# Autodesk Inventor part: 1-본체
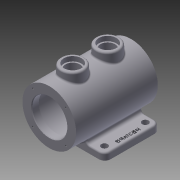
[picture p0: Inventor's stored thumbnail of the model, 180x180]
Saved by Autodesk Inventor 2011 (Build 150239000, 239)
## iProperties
Created: 2014-12
Part Number: 1-본체
Document SubType Name: Modeling
Designer: user
Density: 2.71 g/cm^3
Material: 알루미늄-6061
Mass: 1310.14 g
Surface Area: 1060.2 cm^2
Volume: 483.445 cm^3
Author: user
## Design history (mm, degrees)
sketch "스케치1"
  geometry: L1 (-47.5, 65)-(47.5, 65); L2 (47.5, 65)-(47.5, -65); L3 (47.5, -65)-(-47.5, -65); L4 (-47.5, -65)-(-47.5, 65); 3 further points
  constraints: 8 end point, 2 midpoint, 2 parallel, 1 horizontal, 1 horizontal alignment, 1 perpendicular, 1 vertical alignment
  dimensions: "d0" = 130 distance of L1.end L2.end; "d1" = 95 distance of L2.end L3.end
extrude "돌출1" new body sketch "스케치1" distance "d2" = 12; taper "d3" = 0 deg
sketch "스케치2"
  geometry: L1 (77.5, 50)-(-62.5, 50); L2 (-47.5, 0)-(-47.5, 12) reference; L3 (47.5, 0)-(-47.5, 0) reference; L4 (77.5, 80)-(77.5, 96); L5 (77.5, 96)-(-62.5, 96); L6 (-62.5, 96)-(-62.5, 80); L7 (-62.5, 80)-(-50.5, 80); L8 (-50.5, 80)-(-50.5, 87.5); L9 (-50.5, 87.5)-(65.5, 87.5); L10 (65.5, 87.5)-(65.5, 80); L11 (65.5, 80)-(77.5, 80); 5 further points
  constraints: 18 end point, 6 parallel, 4 midpoint, 2 perpendicular, 2 vertical alignment, 1 collinear, 1 horizontal, 1 horizontal alignment
  dimensions: "d4" = 140 distance of L1.start L1.end; "d5" = 15 distance from line of L2 L1.end; "d6" = 50 distance between parallel lines of L3 L1; "d7" = 12 distance of L10.end L4.start; "d8" = 60 diameter of point (71.5, 80) L1; "d9" = 75 diameter of L9 L1; "d10" = 92 diameter of L5 L1
revolve "회전1" sketch "스케치2" stored, may be unused: angle "d11" = 90 deg
node "작업 평면2"
  node "작업 평면1"
sketch "스케치3"
  geometry: L1 (70, 46)-(70, -46) reference; L2 (-70, 46)-(-70, -46) reference; L3 (-40, -25.923)-(-40, 25.923) reference; L4 (55, -25.923)-(-40, -25.923) reference; L5 (55, 25.923)-(55, -25.923) reference; L6 (-40, 25.923)-(55, 25.923) reference; C1 r 20 at (-30, 0); C2 r 20 at (30, 0); 1 further point
  constraints: 2 centre point, 2 horizontal alignment
  dimensions: "d13" = 40 diameter of C1; "d14" = 40 diameter of C2; "d15" = 40 distance from line of L2 C1.centre; "d16" = 60 distance of C1.centre C2.centre
extrude "돌출2" join sketch "스케치3" stored distance "d17" = 12; taper "d18" = 0 deg
sketch "스케치4"
  geometry: C1 r 20 at (0, 0) reference; C2 r 20 at (60, 0) reference; 1 further point
hole "Hole1" sketch "스케치4" at (0, 0), (60, 0) diameter "d19" = 25; stored, may be unused: countersink angle "d23" = 90 deg, drill point angle "d25" = 118 deg; dims "d20" = 6, "d21" = 30, "d22" = 8, "d24" = 8
chamfer "모따기1" distance "d26" = 1; stored, may be unused: second distance "d27" = 2, angle "d28" = 45 deg
fillet "모깎기1" dims "d29" = 3
fillet "모깎기2" dims "d30" = 5
sketch "스케치5"
  geometry: L1 (0, 0)-(40, 0); L2 (0, 0)-(28.284, -28.284); C1 r 31 at (0, 0) reference; 2 further points
  constraints: 4 end point, 1 coincident, 1 horizontal
  dimensions: "d32" = 40 distance of L1.start L1.end; "d33" = 40 distance of L1.start L2.end; "d34" = 45 deg angle of L2 L1
hole "Hole2" sketch "스케치5" at (28.284, -28.284) diameter "d35" = 3.242; stored, may be unused: countersink angle "d39" = 90 deg, drill point angle "d41" = 118 deg; dims "d36" = 8, "d37" = 4, "d38" = 2, "d40" = 10
sketch "스케치6"
  geometry: L1 (0, 0)-(-40, 0); L2 (0, 0)-(-28.284, 28.284); C1 r 31 at (0, 0) reference; 2 further points
  constraints: 4 end point, 1 coincident, 1 horizontal
  dimensions: "d45" = 40 distance of L1.start L1.end; "d46" = 40 distance of L1.start L2.end; "d47" = 45 deg angle of L2 L1
hole "Hole3" sketch "스케치6" at (-28.284, 28.284) diameter "d48" = 3.242; stored, may be unused: countersink angle "d52" = 90 deg, drill point angle "d54" = 118 deg; dims "d49" = 8, "d50" = 4, "d51" = 2, "d53" = 10
fillet "모깎기3" dims "d58" = 10
fillet "모깎기4" dims "d59" = 3
sketch "스케치7"
  geometry: L1 (44.5, -38.884)-(44.5, -55) reference; L2 (-44.5, -38.884)-(44.5, -38.884) reference; L3 (-44.5, -55)-(-44.5, -38.884) reference; L4 (37.5, -62)-(-37.5, -62) reference; L5 (37.5, 65)-(-37.5, 65) reference; L6 (47.5, 38.884)-(47.5, 55) reference; C1 r 5.5 at (35, 52); C2 r 5.5 at (-35, 52); C3 r 5.5 at (35, -52); C4 r 5.5 at (-35, -52); A1 r 7 centre (-37.5, -55) between (-44.5, -55) and (-37.5, -62) reference; A2 r 7 centre (37.5, -55) between (37.5, -62) and (44.5, -55) reference; 1 further point
  constraints: 4 centre point, 2 horizontal alignment, 2 vertical alignment
  dimensions: "d60" = 11 diameter of C1; "d61" = 11 diameter of C2; "d62" = 11 diameter of C3; "d63" = 11 diameter of C4; "d66" = 12.5 distance from line of L6 C1.centre; "d67" = 104 distance of C3.centre C1.centre; "d69" = 70 distance of C2.centre C1.centre; "d70" = 13 vertical distance of L5.start C1.centre
hole "Hole4" sketch "스케치7" at (-35, -52), (35, -52), (-35, 52), (35, 52) diameter "d71" = 11; stored, may be unused: countersink angle "d75" = 90 deg, drill point angle "d77" = 118 deg; dims "d72" = 8, "d73" = 4, "d74" = 2, "d76" = 10
fillet "모깎기5" dims "d78" = 3
sketch "스케치8"
  geometry: L1 (-22.5, -54)-(22.5, -54); L2 (22.5, -54)-(22.5, -60); L3 (22.5, -60)-(-22.5, -60); L4 (-22.5, -60)-(-22.5, -54); L5 (-22.5, -57)-(22.5, -57); L6 (0, -54)-(0, -60); L7 (-37.5, -65)-(37.5, -65) reference; C1 r 5.5 at (-35, -52) reference; 1 further point
  constraints: 4 end point, 4 midpoint, 2 other
  dimensions: "d83" = 8 distance between parallel lines of L7 L5; "d84" = 35 distance from line of C1.centre L6; "d85" = 6 distance between parallel lines of L3 L1; "d86" = 45 distance between parallel lines of L2 L4
feature "엠보싱1" sketch "스케치8" dims "d0" = 130, "d1" = 95, "d10" = 92, "d87" = 1, "d88" = 0
fillet "모깎기6" dims "d89" = 3
fillet "모깎기7" dims "d90" = 3
node "솔리드1"
pattern_circular "원형 패턴1" dims angle "d43" = 360 deg
pattern_circular "원형 패턴2" dims angle "d56" = 360 deg
node "투영된 루프1"
node "투영된 루프2"
node "투영된 루프3"
other parameters: "d12" = 14
